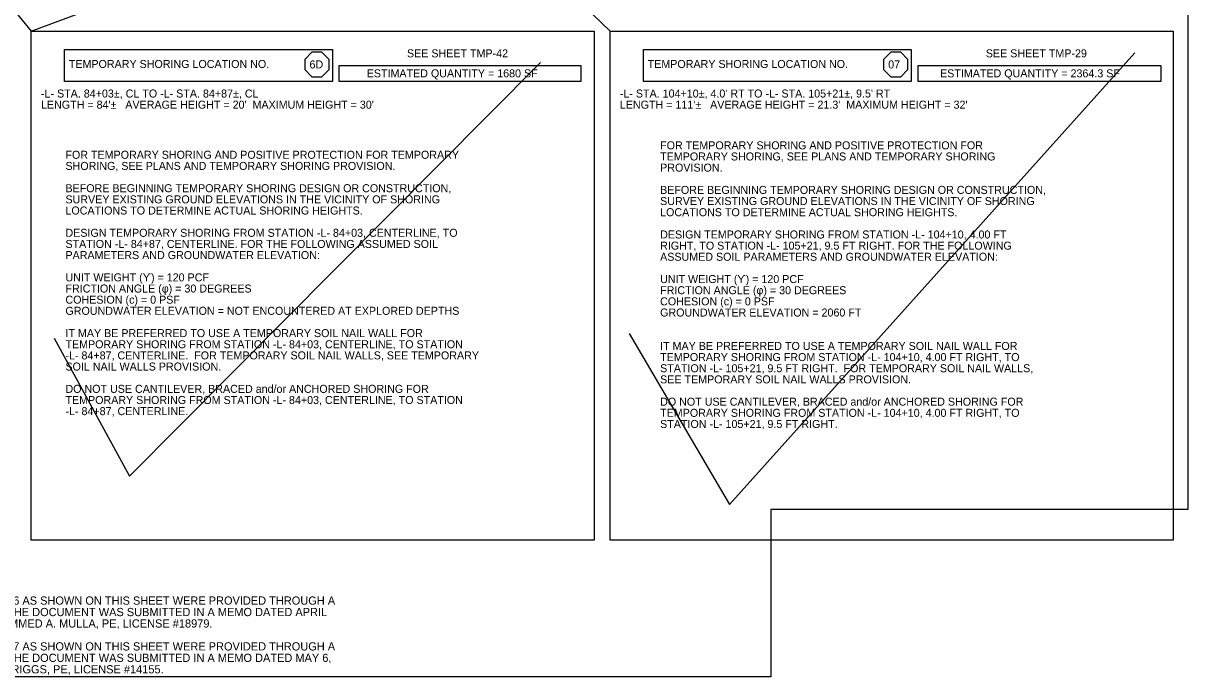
# Model space of a CAD drawing. Extents: x 2487012 to 2497594, y 369516 to 371986.
# Drawn here: x 2493067 to 2494058, y 370242 to 370799 of the extents above; entities that cross this region are included whole.
import ezdxf

# ---------------------------------------------------------------- set-up
doc = ezdxf.new("R2010")
doc.units = 0
for name, color, linetype in [('Scratch_Level_2', 7, 'Continuous'), ('Scratch_Level_6', 7, 'Continuous'), ('TC LABEL TEMP SHORING', 7, 'Continuous'), ('TC SHEET BORDER LINE THIN', 7, 'Continuous'), ('TC SHEET LAYOUT SHAPE', 7, 'Continuous'), ('TC SHEET TEXT', 7, 'Continuous')]:
    doc.layers.add(name, color=color, linetype=linetype)

msp = doc.modelspace()

# ---------------------------------------------------------------- linework, layer by layer
at = {"layer": 'Scratch_Level_2'}
for points in [[(2493582.88, 370534.68), (2493668.16, 370389), (2494013.3, 370773.72)], [(2493092.99, 370530.57), (2493157.36, 370413.06), (2493507.32, 370765.59)]]:
    msp.add_lwpolyline(points, dxfattribs=at)
at = {"layer": 'Scratch_Level_6'}
msp.add_lwpolyline([(2492568.34, 371282.27), (2492580.66, 371239.13), (2492982.22, 371433.43), (2493073.56, 371239.13), (2493388.33, 371445.42), (2493566.46, 371239.13), (2492395.04, 370955.22), (2492580.66, 370792.26), (2492940.95, 370953.89), (2493073.56, 370792.26), (2493429.6, 370924.58), (2493566.46, 370792.26)], dxfattribs=at)
at = {"layer": 'TC LABEL TEMP SHORING'}
for p, q in [((2493312.52, 370774.3), (2493306.43, 370768.13)), ((2493306.43, 370768.13), (2493306.43, 370759.41)), ((2493321.13, 370774.3), (2493312.52, 370774.3)), ((2493327.22, 370768.13), (2493321.13, 370774.3)), ((2493327.22, 370759.41), (2493327.22, 370768.13)), ((2493805.42, 370774.3), (2493799.33, 370768.13)), ((2493799.33, 370768.13), (2493799.33, 370759.41)), ((2493814.03, 370774.3), (2493805.42, 370774.3)), ((2493820.11, 370768.13), (2493814.03, 370774.3)), ((2493820.11, 370759.41), (2493820.11, 370768.13)), ((2493306.43, 370759.41), (2493312.52, 370753.24)), ((2493321.13, 370753.24), (2493327.22, 370759.41)), ((2493799.33, 370759.41), (2493805.42, 370753.24)), ((2493814.03, 370753.24), (2493820.11, 370759.41)), ((2493312.52, 370753.24), (2493321.13, 370753.24)), ((2493805.42, 370753.24), (2493814.03, 370753.24))]:
    msp.add_line(p, q, dxfattribs=at)
at = {"layer": 'TC SHEET BORDER LINE THIN'}
for points in [[(2493073.56, 370792.26), (2493553, 370792.26), (2493553, 370358.63), (2493073.56, 370358.63)], [(2493566.46, 370792.26), (2494045.9, 370792.26), (2494045.9, 370358.63), (2493566.46, 370358.63)], [(2493102.05, 370776.68), (2493330.1, 370776.68), (2493330.1, 370749.42), (2493102.05, 370749.42)], [(2493594.95, 370776.68), (2493823, 370776.68), (2493823, 370749.42), (2493594.95, 370749.42)], [(2493335.87, 370763.05), (2493541.65, 370763.05), (2493541.65, 370749.42), (2493335.87, 370749.42)], [(2493828.76, 370763.05), (2494035.56, 370763.05), (2494035.56, 370749.42), (2493828.76, 370749.42)]]:
    msp.add_lwpolyline(points, close=True, dxfattribs=at)
at = {"layer": 'TC SHEET LAYOUT SHAPE'}
msp.add_lwpolyline([(2492568.34, 370690.84), (2492568.34, 371000.16), (2492568.34, 371272.27), (2492578.34, 371282.27), (2493021.36, 371282.27), (2493492.34, 371282.27), (2493813.34, 371282.27), (2493813.34, 371202.27), (2493898.34, 371202.27), (2493898.34, 371250.27), (2494058.34, 371250.27), (2494058.34, 370915.3), (2494058.34, 370636.1), (2494058.34, 370384.77), (2493703.34, 370384.77), (2493703.34, 370242.27), (2493330.16, 370242.27), (2493160.7, 370242.27), (2492807.92, 370242.27), (2492568.34, 370242.27)], close=True, dxfattribs=at)

# ---------------------------------------------------------------- texts
at = {"layer": 'TC LABEL TEMP SHORING'}
for s, p in [('6D', (2493310.54, 370760.41)), ('07', (2493803.31, 370760.41))]:
    msp.add_text(s, height=6.814, dxfattribs=at).set_placement(p)
at = {"layer": 'TC SHEET BORDER LINE THIN'}
for s, height, p in [('FOR TEMPORARY SHORING AND POSITIVE PROTECTION FOR', 6.8137, (2493609.1, 370691.52)), ('FOR TEMPORARY SHORING AND POSITIVE PROTECTION FOR TEMPORARY ', 6.8137, (2493102.73, 370683.47)), ('TEMPORARY SHORING, SEE PLANS AND TEMPORARY SHORING', 6.8137, (2493609.1, 370682.03)), ('SHORING, SEE PLANS AND TEMPORARY SHORING PROVISION.', 6.8137, (2493102.73, 370673.97)), ('PROVISION.', 6.814, (2493609.1, 370672.53)), ('BEFORE BEGINNING TEMPORARY SHORING DESIGN OR CONSTRUCTION, ', 6.8137, (2493102.73, 370654.98)), ('BEFORE BEGINNING TEMPORARY SHORING DESIGN OR CONSTRUCTION,', 6.8137, (2493609.1, 370653.54)), ('SURVEY EXISTING GROUND ELEVATIONS IN THE VICINITY OF SHORING ', 6.8137, (2493102.73, 370645.49)), ('SURVEY EXISTING GROUND ELEVATIONS IN THE VICINITY OF SHORING', 6.8137, (2493609.1, 370644.05)), ('LOCATIONS TO DETERMINE ACTUAL SHORING HEIGHTS.', 6.8137, (2493102.73, 370635.99)), ('LOCATIONS TO DETERMINE ACTUAL SHORING HEIGHTS.', 6.8137, (2493609.1, 370634.55)), ('DESIGN TEMPORARY SHORING FROM STATION -L- 84+03, CENTERLINE, TO ', 6.8137, (2493102.73, 370617)), ('DESIGN TEMPORARY SHORING FROM STATION -L- 104+10, 4.00 FT', 6.8137, (2493609.1, 370615.56)), ('STATION -L- 84+87, CENTERLINE. FOR THE FOLLOWING ASSUMED SOIL ', 6.8137, (2493102.73, 370607.51)), ('RIGHT, TO STATION -L- 105+21, 9.5 FT RIGHT. FOR THE FOLLOWING', 6.8137, (2493609.1, 370606.07)), ('PARAMETERS AND GROUNDWATER ELEVATION:', 6.8137, (2493102.73, 370598.02)), ('ASSUMED SOIL PARAMETERS AND GROUNDWATER ELEVATION:', 6.8137, (2493609.1, 370596.58)), ('UNIT WEIGHT (ϒ) = 120 PCF', 6.8137, (2493102.73, 370579.03)), ('UNIT WEIGHT (ϒ) = 120 PCF', 6.8137, (2493609.1, 370577.59)), ('FRICTION ANGLE (φ) = 30 DEGREES', 6.8137, (2493102.73, 370569.53)), ('FRICTION ANGLE (φ) = 30 DEGREES', 6.8137, (2493609.1, 370568.09)), ('COHESION (c) = 0 PSF', 6.8137, (2493102.73, 370560.04)), ('COHESION (c) = 0 PSF', 6.8137, (2493609.1, 370558.6)), ('GROUNDWATER ELEVATION = NOT ENCOUNTERED AT EXPLORED DEPTHS', 6.8137, (2493102.73, 370550.54)), ('GROUNDWATER ELEVATION = 2060 FT', 6.8137, (2493609.1, 370549.1)), ('IT MAY BE PREFERRED TO USE A TEMPORARY SOIL NAIL WALL FOR ', 6.8137, (2493102.73, 370531.56)), ('TEMPORARY SHORING FROM STATION -L- 84+03, CENTERLINE, TO STATION ', 6.8137, (2493102.73, 370522.06)), ('-L- 84+87, CENTERLINE.  FOR TEMPORARY SOIL NAIL WALLS, SEE TEMPORARY ', 6.8137, (2493102.73, 370512.57)), ('IT MAY BE PREFERRED TO USE A TEMPORARY SOIL NAIL WALL FOR', 6.8137, (2493609.1, 370520.62)), ('SOIL NAIL WALLS PROVISION.', 6.8137, (2493102.73, 370503.07)), ('TEMPORARY SHORING FROM STATION -L- 104+10, 4.00 FT RIGHT, TO', 6.8137, (2493609.1, 370511.13)), ('STATION -L- 105+21, 9.5 FT RIGHT.  FOR TEMPORARY SOIL NAIL WALLS,', 6.8137, (2493609.1, 370501.63)), ('SEE TEMPORARY SOIL NAIL WALLS PROVISION.', 6.8137, (2493609.1, 370492.14)), ('DO NOT USE CANTILEVER, BRACED and/or ANCHORED SHORING FOR ', 6.8137, (2493102.73, 370484.08)), ('TEMPORARY SHORING FROM STATION -L- 84+03, CENTERLINE, TO STATION ', 6.8137, (2493102.73, 370474.59)), ('DO NOT USE CANTILEVER, BRACED and/or ANCHORED SHORING FOR', 6.8137, (2493609.1, 370473.15)), ('-L- 84+87, CENTERLINE.', 6.8137, (2493102.73, 370465.09)), ('TEMPORARY SHORING FROM STATION -L- 104+10, 4.00 FT RIGHT, TO', 6.8137, (2493609.1, 370463.65)), ('STATION -L- 105+21, 9.5 FT RIGHT.', 6.8137, (2493609.1, 370454.16))]:
    msp.add_text(s, height=height, dxfattribs=at).set_placement(p)
at = {"layer": 'TC SHEET TEXT'}
for s, height, p in [('SEE SHEET TMP-42', 6.8137, (2493393.55, 370769.88)), ('SEE SHEET TMP-29', 6.8137, (2493886.43, 370769.88)), ('TEMPORARY SHORING LOCATION NO.', 6.8137, (2493105.62, 370760.81)), ('TEMPORARY SHORING LOCATION NO.', 6.8137, (2493598.51, 370760.81)), ('ESTIMATED QUANTITY = 1680 SF', 6.8137, (2493359.26, 370752.83)), ('ESTIMATED QUANTITY = 2364.3 SF', 6.8137, (2493847.46, 370752.83)), ('-L- STA. 84+03±, CL TO -L- STA. 84+87±, CL', 6.8137, (2493081.9, 370735.64)), ("-L- STA. 104+10±, 4.0' RT TO -L- STA. 105+21±, 9.5' RT", 6.8137, (2493574.79, 370735.64)), ("LENGTH = 84'±   AVERAGE HEIGHT = 20'  MAXIMUM HEIGHT = 30'", 6.8137, (2493081.9, 370726.15)), ("LENGTH = 111'±   AVERAGE HEIGHT = 21.3'  MAXIMUM HEIGHT = 32'", 6.8137, (2493574.79, 370726.15)), ('THE TEMPORARY SHORING NOTES FOR LOCATIONS 5A THRU 6 AS SHOWN ON THIS SHEET WERE PROVIDED THROUGH A ', 7, (2492772.23, 370303.64)), ('SEALED DOCUMENT FROM THE GEOTECHNICAL ENGINEER.  THE DOCUMENT WAS SUBMITTED IN A MEMO DATED APRIL ', 7, (2492772.23, 370293.88)), ('23, 2026 AND SEALED BY A PROFESSIONAL ENGINEER, MOHAMMED A. MULLA, PE, LICENSE #18979.', 7, (2492772.23, 370284.13)), ('THE TEMPORARY SHORING NOTES FOR LOCATIONS 6B THRU 7 AS SHOWN ON THIS SHEET WERE PROVIDED THROUGH A ', 7, (2492772.23, 370264.62)), ('SEALED DOCUMENT FROM THE GEOTECHNICAL ENGINEER.  THE DOCUMENT WAS SUBMITTED IN A MEMO DATED MAY 6, ', 7, (2492772.23, 370254.87)), ('2026 AND SEALED BY A PROFESSIONAL ENGINEER, ABNER F. RIGGS, PE, LICENSE #14155.', 7, (2492772.23, 370245.11))]:
    msp.add_text(s, height=height, dxfattribs=at).set_placement(p)

doc.saveas('drawing.dxf')
